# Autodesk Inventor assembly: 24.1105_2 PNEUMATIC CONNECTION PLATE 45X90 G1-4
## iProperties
Created: 2007-06
Part Number: 24.1105_2 PNEUMATIC CONNECTION PLATE 45X90 G1-4
Document SubType Name: Assembly
Designer: Andy Moles
Author: Andy Moles
